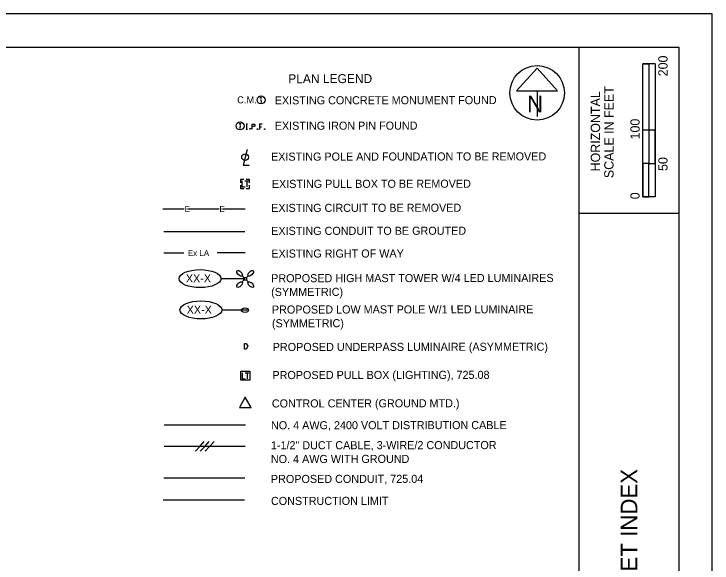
# Model space of a CAD drawing. Extents: x 310 to 1844719, y 48 to 494239.
# Drawn here: x 1838148 to 1840250, y 492586 to 494239 of the extents above; entities that cross this region are included whole.
import ezdxf

# ---------------------------------------------------------------- set-up
doc = ezdxf.new("R2010")
doc.units = 0
for name, color, linetype in [('BR_X_SV_Abut_Text', 7, 'Continuous'), ('BR_X_SV_Bottom_of_Beam_Text', 7, 'Continuous'), ('BR_X_SV_Deck_Top_Text', 7, 'Continuous'), ('BR_X_SV_Pier_Cap_Top_Text', 7, 'Continuous'), ('Center line', 7, 'Continuous'), ('Clear Zones 30ft', 7, 'Continuous'), ('Geohazard Areas', 7, 'Continuous'), ('LT_P_Control_Center', 7, 'Continuous'), ('LT_P_PullBox', 7, 'Continuous'), ('PV_X_Curb', 7, 'Continuous'), ('RD_X_Concrete_Barrier', 7, 'Continuous'), ('RW_X_Esmt_LA', 7, 'Continuous'), ('SC_Scratch2', 7, 'Continuous'), ('SG_X_PullBox', 7, 'Continuous'), ('Shoulder lines', 7, 'Continuous'), ('SN_X_Public', 7, 'Continuous'), ('SV_P_Mon_Cells_Set', 7, 'Continuous'), ('UT_P_Electric_Cells', 7, 'Continuous'), ('VG_X_Tree_Line_Lt', 7, 'Continuous')]:
    doc.layers.add(name, color=color, linetype=linetype)

msp = doc.modelspace()

# ---------------------------------------------------------------- linework, layer by layer
at = {"layer": 'BR_X_SV_Abut_Text'}
msp.add_line((1838843.4, 492841.7), (1838598.9, 492841.7), dxfattribs=at)
at = {"layer": 'BR_X_SV_Bottom_of_Beam_Text'}
for p, q in [((1838891.6, 493981.1), (1838892.1, 493972.3)), ((1838828.6, 493902.8), (1838827.7, 493894))]:
    msp.add_line(p, q, dxfattribs=at)
for points in [[(1838847.3, 493891.9), (1838850.9, 493891.8)], [(1838847.6, 493907.8), (1838851.2, 493907.8)], [(1838849.1, 493891.8), (1838849.4, 493907.8)], [(1838858.7, 493893.8), (1838859.3, 493893.8), (1838859.6, 493893.5), (1838859.9, 493893), (1838859.9, 493892.4), (1838859.6, 493891.9), (1838859.2, 493891.6), (1838858.7, 493891.6), (1838858.4, 493891.9), (1838858, 493892.4), (1838858.1, 493893), (1838858.4, 493893.5), (1838858.7, 493893.8)], [(1838864.7, 493891.5), (1838865.1, 493907.5), (1838870.4, 493907.4), (1838870.9, 493907.3), (1838871.7, 493907), (1838872, 493906.7), (1838872.3, 493906.5), (1838872.7, 493905.8), (1838873.1, 493905.2), (1838873.3, 493904.2), (1838873.2, 493902.7), (1838873.1, 493902.2), (1838872.9, 493901.4), (1838872.4, 493900.6), (1838872, 493900.2), (1838871.6, 493899.9), (1838871.1, 493899.7), (1838870.2, 493899.6), (1838864.9, 493899.7)], [(1838881.2, 493893.3), (1838881.8, 493893.3), (1838882.1, 493893.1), (1838882.4, 493892.6), (1838882.4, 493891.9), (1838882.1, 493891.4), (1838881.7, 493891.2), (1838881.2, 493891.2), (1838880.8, 493891.4), (1838880.5, 493892), (1838880.5, 493892.6), (1838880.9, 493893.1), (1838881.2, 493893.3)], [(1838895.1, 493906.9), (1838887.5, 493907.1), (1838887.2, 493891.1)], [(1838887.4, 493899.3), (1838892.8, 493899.2)], [(1838902.7, 493892.9), (1838903.3, 493892.9), (1838903.6, 493892.6), (1838903.9, 493892.1), (1838903.9, 493891.5), (1838903.5, 493891), (1838903.2, 493890.8), (1838902.7, 493890.8), (1838902.3, 493891), (1838902, 493891.5), (1838902, 493892.2), (1838902.4, 493892.7), (1838902.7, 493892.9)]]:
    msp.add_lwpolyline(points, dxfattribs=at)
for centre, radius in [((1838891.7, 493979.9), 12), ((1838891.4, 493986.4), 1.6), ((1838828.5, 493901.6), 12), ((1838829.1, 493908.1), 1.6)]:
    msp.add_circle(centre, radius, dxfattribs=at)
at = {"layer": 'BR_X_SV_Deck_Top_Text'}
msp.add_line((1838843.4, 493582.8), (1838598.8, 493582.8), dxfattribs=at)
at = {"layer": 'BR_X_SV_Pier_Cap_Top_Text'}
msp.add_line((1838841.7, 492775.7), (1838597.1, 492775.7), dxfattribs=at)
at = {"layer": 'Center line'}
msp.add_circle((1839723, 494001.2), 82, dxfattribs=at)
at = {"layer": 'Clear Zones 30ft'}
for p, q in [((1839849.7, 489938.7), (1839849.7, 494138.7)), ((1839849.7, 493638.7), (1840149.7, 493638.7))]:
    msp.add_line(p, q, dxfattribs=at)
msp.add_lwpolyline([(1833749.7, 494138.7), (1840149.7, 494138.7), (1840149.7, 489938.7), (1833749.7, 489938.7)], close=True, dxfattribs=at)
at = {"layer": 'Geohazard Areas'}
for p, q in [((1840041, 493688.7), (1840041, 494088.7)), ((1840078.5, 494088.7), (1840041, 494088.7)), ((1840041, 493888.7), (1840041, 494088.7)), ((1840041, 494088.7), (1840059.7, 494088.7)), ((1840059.7, 494088.7), (1840059.9, 494088.7)), ((1840059.9, 494088.7), (1840059.9, 493888.7)), ((1840078.5, 494088.7), (1840078.5, 493688.7)), ((1840059.9, 493888.7), (1840041, 493888.7)), ((1840078.4, 493888.7), (1840059.7, 493888.7)), ((1840059.7, 493888.7), (1840059.7, 493788.7)), ((1840078.4, 493788.7), (1840078.4, 493888.7)), ((1840059.7, 493788.7), (1840041, 493788.7)), ((1840041, 493788.7), (1840041, 493688.7)), ((1840059.7, 493788.7), (1840078.4, 493788.7)), ((1840059.7, 493688.7), (1840059.7, 493788.7)), ((1840078.5, 493688.7), (1840041, 493688.7)), ((1840041, 493688.7), (1840059.7, 493688.7))]:
    msp.add_line(p, q, dxfattribs=at)
at = {"layer": 'LT_P_Control_Center'}
for p, q in [((1838839.9, 493445.3), (1838834.8, 493450.4)), ((1838848, 493445.3), (1838853.2, 493450.4)), ((1838839.9, 493437.2), (1838834.8, 493432)), ((1838853.2, 493432), (1838848, 493437.2))]:
    msp.add_line(p, q, dxfattribs=at)
for points in [[(1838839.9, 493445.3), (1838848, 493445.3), (1838848, 493437.2), (1838839.9, 493437.2)], [(1838841.6, 493229.8), (1838841.5, 493247.3), (1838846.8, 493247.3), (1838852.1, 493238.6), (1838846.8, 493229.8)]]:
    msp.add_lwpolyline(points, close=True, dxfattribs=at)
for centre, major_axis in [((1838827.1, 493458.1), (7.67, -7.68)), ((1838860.8, 493458.1), (7.67, 7.68)), ((1838827.1, 493424.3), (-7.67, -7.68)), ((1838860.9, 493424.4), (7.68, -7.67))]:
    msp.add_ellipse(centre, major_axis=major_axis, ratio=0.5, dxfattribs=at)
at = {"layer": 'LT_P_PullBox'}
for p, q in [((1838844.9, 493001.2), (1838600.4, 493001.2)), ((1838707.4, 492937.1), (1838720.6, 492952)), ((1838722.2, 492937.1), (1838735.4, 492952)), ((1838736.9, 492937.1), (1838750.2, 492952)), ((1838844.4, 492937.1), (1838599.9, 492937.1)), ((1838694.1, 492922.3), (1838707.4, 492937.1)), ((1838708.9, 492922.3), (1838722.2, 492937.1)), ((1838723.7, 492922.3), (1838736.9, 492937.1))]:
    msp.add_line(p, q, dxfattribs=at)
at = {"layer": 'PV_X_Curb'}
for p, q in [((1838599.1, 493519.9), (1838658.9, 493519.9)), ((1838843.6, 493519.9), (1838759.9, 493519.9))]:
    msp.add_line(p, q, dxfattribs=at)
at = {"layer": 'RD_X_Concrete_Barrier'}
msp.add_line((1838843.7, 493727), (1838843.7, 493727), dxfattribs=at)
for points in [[(1838840.1, 493740.5), (1838830.2, 493740.5), (1838830.2, 493730.6)], [(1838833.9, 493736), (1838833.9, 493718), (1838843.7, 493718)], [(1838843.2, 493736), (1838854.4, 493736)], [(1838857.2, 493730.6), (1838857.2, 493740.5), (1838847.3, 493740.5)], [(1838847.3, 493713.5), (1838857.2, 493713.5), (1838857.2, 493723.4)], [(1838848.9, 493736), (1838848.9, 493718)], [(1838830.2, 493723.4), (1838830.2, 493713.5), (1838840.1, 493713.5)]]:
    msp.add_lwpolyline(points, dxfattribs=at)
at = {"layer": 'RW_X_Esmt_LA'}
msp.add_lwpolyline([(1833449.7, 489838.7), (1840249.7, 489838.7), (1840249.7, 494238.7), (1833449.7, 494238.7)], close=True, dxfattribs=at)
at = {"layer": 'SC_Scratch2'}
msp.add_lwpolyline([(1838826.7, 493054), (1838862.1, 493054), (1838844.3, 493085.2)], close=True, dxfattribs=at)
at = {"layer": 'SG_X_PullBox'}
for p, q in [((1838595.8, 493651.7), (1838660.5, 493651.7)), ((1838672.2, 493651.7), (1838765.3, 493651.7)), ((1838776.2, 493651.7), (1838843.9, 493651.7))]:
    msp.add_line(p, q, dxfattribs=at)
at = {"layer": 'Shoulder lines'}
for p, q in [((1839723, 494075.9), (1839661.4, 494007.7)), ((1839784.5, 494007.7), (1839723, 494075.9)), ((1839661.4, 494007.7), (1839784.5, 494007.7)), ((1839723, 494007.7), (1839723, 493930.3))]:
    msp.add_line(p, q, dxfattribs=at)
msp.add_circle((1839723, 494001.2), 82, dxfattribs=at)
at = {"layer": 'SN_X_Public'}
msp.add_lwpolyline([(1838849.7, 493830.5), (1838837.5, 493784), (1838855.9, 493784)], dxfattribs=at)
msp.add_circle((1838843.6, 493807.5), 10.1, dxfattribs=at)
at = {"layer": 'SV_P_Mon_Cells_Set'}
msp.add_ellipse((1838843.3, 493347), major_axis=(10.8, 0), ratio=0.625, dxfattribs=at)
at = {"layer": 'UT_P_Electric_Cells'}
msp.add_line((1838844.3, 493149.8), (1838844.3, 493149.8), dxfattribs=at)
msp.add_lwpolyline([(1838830.8, 493163.3), (1838857.8, 493163.3), (1838857.8, 493136.3), (1838830.8, 493136.3)], close=True, dxfattribs=at)
for points in [[(1838834.5, 493158.8), (1838834.5, 493140.8), (1838844.3, 493140.8)], [(1838843.9, 493158.8), (1838855.1, 493158.8)], [(1838849.6, 493158.8), (1838849.6, 493140.8)]]:
    msp.add_lwpolyline(points, dxfattribs=at)
at = {"layer": 'VG_X_Tree_Line_Lt'}
for p, q in [((1838843.4, 493441.2), (1838771.3, 493441.1)), ((1838850.9, 493347), (1838773.7, 493346.9))]:
    msp.add_line(p, q, dxfattribs=at)
for centre in [(1838708.3, 493442.1), (1838710.7, 493347.9)]:
    msp.add_ellipse(centre, major_axis=(63.1, 0.1), ratio=0.428726, dxfattribs=at)

# ---------------------------------------------------------------- texts
at = {"layer": 'BR_X_SV_Bottom_of_Beam_Text'}
msp.add_text('C.M.', height=21, dxfattribs=at).set_placement((1838819.8, 493969.7))
at = {"layer": 'Geohazard Areas'}
for s, height, p in [('200', 28, (1840115.8, 494051.1)), ('SCALE IN FEET', 28, (1839953.2, 493744.6)), ('HORIZONTAL', 28, (1839912.7, 493764.8)), ('100', 28, (1840031.8, 493861.1)), ('50', 28, (1840115.8, 493766.1)), ('0', 28, (1840031.8, 493681)), ('ROS-23-13.06 SCHEMATIC/ SHEET INDEX', 50, (1840024.7, 491542.8))]:
    msp.add_text(s, height=height, rotation=90, dxfattribs=at).set_placement(p)
at = {"layer": 'PV_X_Curb'}
msp.add_text('Ex LA', height=17.94, dxfattribs=at).set_placement((1838671.4, 493510.2))
at = {"layer": 'SG_X_PullBox'}
for p in [(1838661.6, 493642.5), (1838766.7, 493642.5)]:
    msp.add_text('E', height=17.9, dxfattribs=at).set_placement(p)
at = {"layer": 'Shoulder lines'}
msp.add_text('N', height=50, dxfattribs=at).set_placement((1839692.7, 493942.9))
at = {"layer": 'VG_X_Tree_Line_Lt'}
for s, height, p in [('PLAN LEGEND', 27, (1838973.6, 494030.4)), ('EXISTING CONCRETE MONUMENT FOUND', 24.3, (1838933, 493966.6)), ('EXISTING IRON PIN FOUND', 24.3, (1838933, 493890.1)), ('EXISTING POLE AND FOUNDATION TO BE REMOVED', 24.3, (1838921.8, 493797.1)), ('EXISTING PULL BOX TO BE REMOVED', 24.3, (1838924.1, 493715.1)), ('EXISTING CIRCUIT TO BE REMOVED', 24.3, (1838922.3, 493642.8)), ('EXISTING CONDUIT TO BE GROUTED', 24.3, (1838922.4, 493573.6)), ('EXISTING RIGHT OF WAY', 24.3, (1838922.7, 493505.3)), ('XX-X', 24.3, (1838665.4, 493430.7)), ('PROPOSED HIGH MAST TOWER W/4 LED LUMINAIRES ', 24.3, (1838922.2, 493431.2)), ('(SYMMETRIC)', 24.3, (1838922.2, 493389.9)), ('XX-X', 24.3, (1838667.8, 493336.4)), ('PROPOSED LOW MAST POLE W/1 LED LUMINAIRE ', 24.3, (1838924.5, 493336.9)), ('(SYMMETRIC)', 24.3, (1838924.6, 493295.6)), ('PROPOSED UNDERPASS LUMINAIRE (ASYMMETRIC)', 24.3, (1838926.9, 493224.2)), ('PROPOSED PULL BOX (LIGHTING), 725.08', 24.3, (1838926.1, 493139.7)), ('CONTROL CENTER (GROUND MTD.)', 24.3, (1838924.3, 493054.3)), ('NO. 4 AWG, 2400 VOLT DISTRIBUTION CABLE', 24.3, (1838921.7, 492988.5)), ('1-1/2" DUCT CABLE, 3-WIRE/2 CONDUCTOR', 24.3, (1838921.4, 492928.3)), ('NO. 4 AWG WITH GROUND', 24.3, (1838921.4, 492887)), ('PROPOSED CONDUIT, 725.04', 24.3, (1838921.5, 492826.9)), ('CONSTRUCTION LIMIT', 24.3, (1838921.6, 492760.8))]:
    msp.add_text(s, height=height, rotation=0.0609, dxfattribs=at).set_placement(p)

doc.saveas('drawing.dxf')
